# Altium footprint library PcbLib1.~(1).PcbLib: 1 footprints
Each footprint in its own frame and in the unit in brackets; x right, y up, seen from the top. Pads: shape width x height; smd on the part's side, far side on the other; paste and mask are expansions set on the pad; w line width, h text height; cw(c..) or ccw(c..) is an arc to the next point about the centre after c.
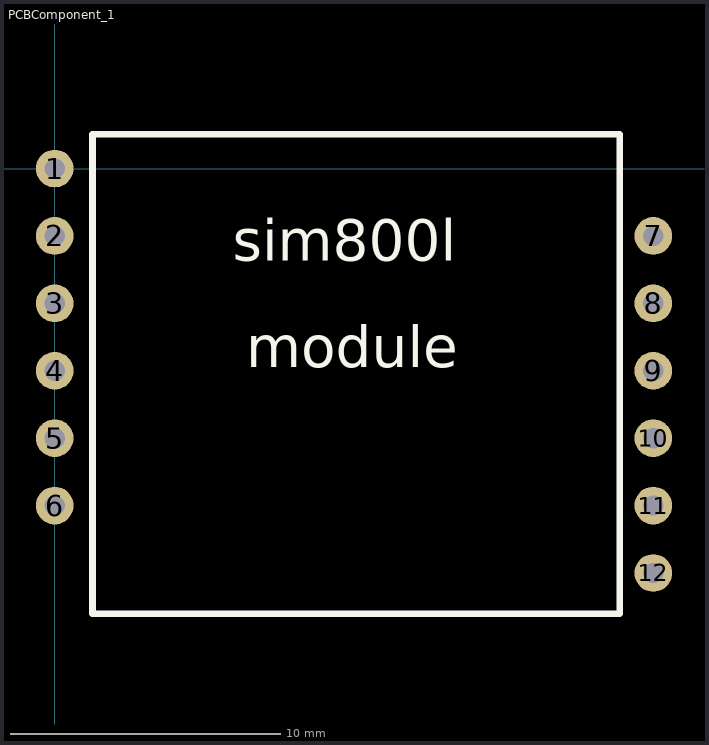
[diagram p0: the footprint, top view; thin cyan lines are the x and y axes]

## PCBComponent_1 [mm]
pads (12):
  round 1.4 hole 0.75: 1(0,0) 2(0,-2.5) 3(0,-5) 4(0,-7.5) 5(0,-10) 6(0,-12.5) 7(22.2,-2.5) 8(22.2,-5) 9(22.2,-7.5) 10(22.2,-10) 11(22.2,-12.5) 12(22.2,-15)
Top Overlay:
  lines w0.254: 1.397,-16.51 20.955,-16.51 20.955,1.27 19.939,1.27 1.397,1.27 1.397,-16.51
  text "module" at 7.112,-7.366 h1.52
  text "sim800l" at 6.604,-3.429 h1.52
